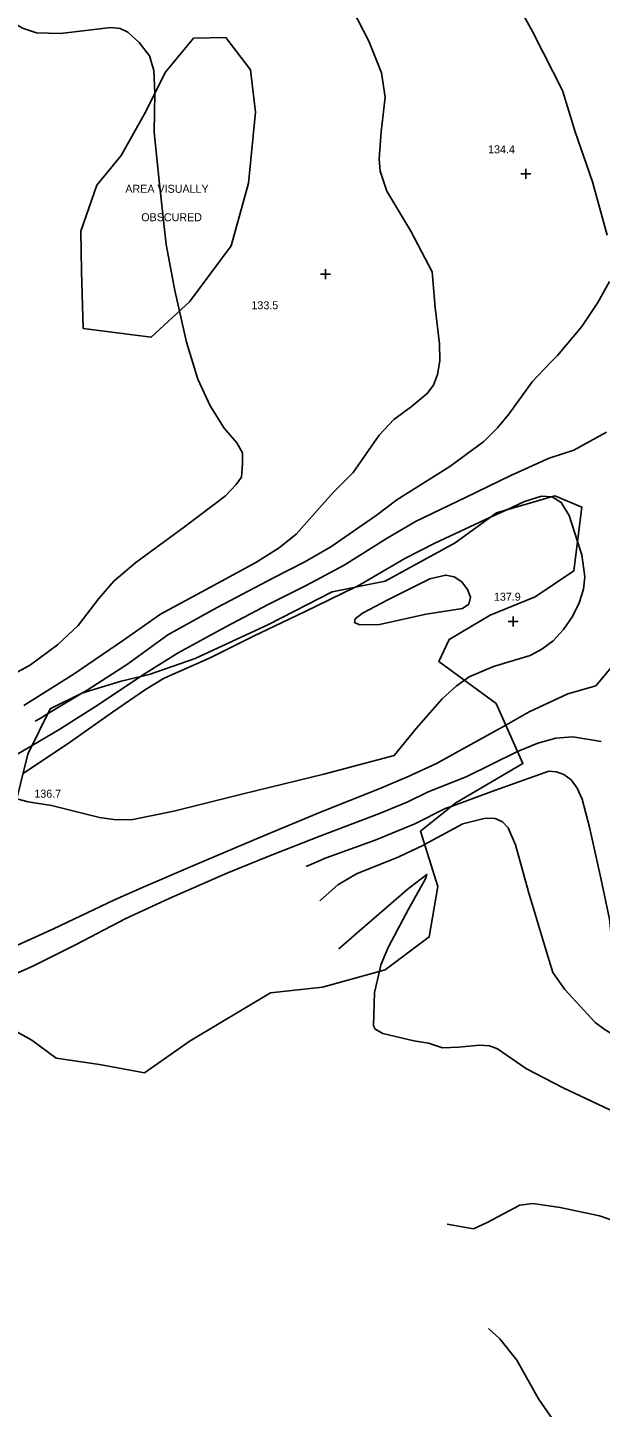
# Model space of a CAD drawing. Extents: x 1467615 to 2003689, y 770235 to 1108726.
# Drawn here: x 2002350.5 to 2002493.7, y 770841.8 to 771186.6 of the extents above; entities that cross this region are included whole.
import ezdxf

# ---------------------------------------------------------------- set-up
doc = ezdxf.new("R2010")
doc.units = 0
for name, color, linetype in [('RD_DTM_Major1', 7, 'Continuous'), ('RD_DTM_Major2', 7, 'Continuous'), ('RD_DTM_Minor1', 7, 'Continuous'), ('RD_DTM_Minor2', 7, 'Continuous'), ('RD_DTM_Obscure', 7, 'Continuous'), ('RD_DTM_Spot_Elev', 7, 'Continuous'), ('RD_TX_Misc1', 7, 'Continuous')]:
    doc.layers.add(name, color=color, linetype=linetype)

msp = doc.modelspace()

# ---------------------------------------------------------------- linework, layer by layer
at = {"layer": 'RD_DTM_Major1'}
for points in [[(2002437.97, 771234.89), (2002438.87, 771233.58), (2002445.32, 771226.37), (2002450.88, 771220.42), (2002458.65, 771210.24), (2002467.21, 771200), (2002472.79, 771192.64), (2002476.77, 771185.62), (2002481.91, 771175.42), (2002484.21, 771170.88), (2002487.38, 771160.55), (2002491.78, 771148.03), (2002495.42, 771134.7)], [(2002496.03, 771123.14), (2002493.09, 771117.87), (2002489.06, 771111.85), (2002483.02, 771104.66), (2002481.25, 771102.86), (2002476.67, 771098.08), (2002470.8, 771090), (2002467.99, 771086.57), (2002464.55, 771083.13), (2002456.12, 771076.93), (2002442.85, 771068.62), (2002437.65, 771064.68), (2002426.32, 771056.84), (2002419.87, 771053.12), (2002412.02, 771049.06), (2002397.94, 771041.69), (2002385.6, 771034.82), (2002375.51, 771027.5), (2002365.42, 771021.06), (2002364.25, 771020.35)], [(2002355.53, 771015.1), (2002353.68, 771013.99), (2002352.47, 771013.3)], [(2002473.03, 771005.67), (2002473.37, 771005.84), (2002478.04, 771007.82), (2002482.57, 771009.07), (2002486.81, 771009.34), (2002493.88, 771008.19)], [(2002465.72, 770861.55), (2002468.59, 770858.95), (2002472.79, 770853.64), (2002478.26, 770844), (2002482.78, 770837.46), (2002487.68, 770830.27), (2002489.58, 770825.77), (2002490.82, 770820.44), (2002492.47, 770804.83), (2002493.14, 770801.64), (2002494.31, 770799.47), (2002496.27, 770797.81), (2002504.44, 770793.62)]]:
    msp.add_lwpolyline(points, dxfattribs=at)
at = {"layer": 'RD_DTM_Major2'}
msp.add_line((2002364.25, 771020.35), (2002355.53, 771015.1), dxfattribs=at)
msp.add_lwpolyline([(2002341.81, 770947.7), (2002352.01, 770952.12), (2002362.55, 770957.4), (2002375.11, 770963.95), (2002385.95, 770968.99), (2002400.14, 770975.21), (2002410.86, 770979.52), (2002423.55, 770984.53), (2002438.54, 770990.19), (2002445.62, 770993.11), (2002450.68, 770995.65), (2002460.15, 770999.38), (2002473.03, 771005.67)], dxfattribs=at)
at = {"layer": 'RD_DTM_Minor1'}
for points in [[(2002430.3, 771193.91), (2002435.8, 771183.21), (2002438.98, 771175.26), (2002439.92, 771169.21), (2002438.94, 771160.49), (2002438.45, 771153.75), (2002438.65, 771150.68), (2002440.32, 771145.73), (2002446.34, 771135.68), (2002451.66, 771125.53), (2002452.44, 771116.65), (2002453.5, 771107.57), (2002453.56, 771103.3), (2002453.03, 771099.88), (2002451.96, 771097.22), (2002450.44, 771095.13), (2002446.45, 771091.82), (2002442.06, 771088.66), (2002438.39, 771084.72), (2002431.93, 771075.43), (2002426.94, 771070.38), (2002417.66, 771059.98), (2002413.45, 771056.62), (2002407.57, 771052.96), (2002398.09, 771047.74), (2002383.73, 771040.05), (2002374.53, 771033.56), (2002362.2, 771025.11), (2002349.57, 771017.23)], [(2002346.15, 771188.23), (2002349.24, 771186.4), (2002352.73, 771185.28), (2002358.73, 771185.06), (2002371.37, 771186.57), (2002373.65, 771186.36), (2002375.57, 771185.44), (2002378.41, 771182.8), (2002380.99, 771179.47), (2002382.07, 771175.83), (2002382.31, 771170.22), (2002382.31, 771170.08)], [(2002388.51, 771115.68), (2002390.27, 771107.93), (2002393.12, 771098.76), (2002396.2, 771092.03), (2002399.64, 771086.51), (2002402.86, 771082.85), (2002404.25, 771080.35), (2002404.25, 771077.56), (2002403.97, 771074.22), (2002402.66, 771072.4), (2002400.04, 771069.59), (2002389.75, 771061.83), (2002377.56, 771052.89), (2002372.08, 771048.25), (2002368.36, 771043.97), (2002363.21, 771037.19), (2002358.02, 771032.38), (2002351.23, 771027.39), (2002340.31, 771021.4), (2002334.23, 771017.87), (2002324.82, 771012.31), (2002317.66, 771007.73)], [(2002495.2, 771085.52), (2002487.08, 771081), (2002480.87, 771078.99), (2002471.48, 771074.73), (2002459.98, 771069.16), (2002447.66, 771063.23), (2002440.44, 771059.04), (2002429.65, 771052.3), (2002420.16, 771047.19), (2002410.7, 771042.4), (2002400.06, 771036.86), (2002388.21, 771030.37), (2002379.53, 771024.94), (2002378.73, 771024.41)], [(2002481.61, 771069.34), (2002479.01, 771069.46), (2002474.76, 771068.16), (2002470.3, 771066.1)], [(2002466.08, 771064.16), (2002464.81, 771063.57), (2002452.37, 771057.78), (2002444.85, 771053.91), (2002433.62, 771047.34), (2002432.38, 771046.74)], [(2002459.73, 771023.53), (2002460.9, 771024.35), (2002467, 771026.91), (2002476.13, 771029.71), (2002479.11, 771031.24), (2002481.94, 771033.35), (2002484.52, 771036.15), (2002486.72, 771039.42), (2002488.42, 771042.89), (2002489.5, 771046.27), (2002489.86, 771049.36), (2002489.09, 771054.84), (2002488.01, 771058.14)], [(2002470.06, 771012.31), (2002475.93, 771015.62), (2002485.61, 771020.09), (2002492.57, 771022.13), (2002496.94, 771027.3)], [(2002351.65, 771007.2), (2002346.26, 771004.03), (2002340.47, 771001.65), (2002335.57, 771000.36), (2002330.18, 770998.85), (2002325.33, 770996.8), (2002320.93, 770992.77), (2002319.36, 770991.29)], [(2002456.63, 770992.09), (2002467.5, 770996.08), (2002480.82, 771000.79), (2002482.72, 771000.63), (2002484.61, 770999.93), (2002486.39, 770998.6), (2002487.95, 770996.56), (2002489.2, 770993.76), (2002491.03, 770986.82), (2002493.79, 770974.07), (2002496.02, 770963.78), (2002497.38, 770950.37), (2002498.08, 770949.09), (2002499.26, 770948.11), (2002503.73, 770946.02), (2002514.91, 770941.81), (2002517.82, 770946.96)], [(2002449.77, 770982.48), (2002459.34, 770987.64), (2002465.01, 770989.08), (2002467.43, 770988.98), (2002469.28, 770988.14), (2002470.63, 770986.66), (2002472.46, 770982.41), (2002475.72, 770970.69), (2002479.97, 770956.5), (2002481.82, 770950.52), (2002484.83, 770946.24), (2002492.41, 770938.02), (2002494.89, 770936.19), (2002500.41, 770932.92), (2002504.77, 770930.82), (2002509.88, 770929.21), (2002515.45, 770928.74), (2002521.24, 770929.81), (2002528.73, 770932.65)], [(2002438.46, 770950.79), (2002437.24, 770945.49), (2002437.02, 770937.15), (2002437.39, 770936.36), (2002439.36, 770935.27), (2002447.11, 770933.43), (2002450.77, 770932.81), (2002454.21, 770931.71), (2002458.28, 770931.85), (2002463.62, 770932.38), (2002466.03, 770932.19), (2002468.01, 770931.44), (2002475.22, 770926.39), (2002484.44, 770921.7), (2002498.9, 770914.88), (2002505.92, 770910.8), (2002515.6, 770903.66), (2002525.72, 770895.19), (2002535.45, 770885.57), (2002545.38, 770875.06), (2002549.34, 770870.1), (2002558.62, 770864.92), (2002560.82, 770863.55)], [(2002455.45, 770887.59), (2002462, 770886.45), (2002465.43, 770888.01), (2002473.56, 770892.39), (2002476.83, 770892.76), (2002483.67, 770891.8), (2002493.47, 770889.68), (2002497.86, 770888.21)]]:
    msp.add_lwpolyline(points, dxfattribs=at)
at = {"layer": 'RD_DTM_Minor2'}
msp.add_line((2002470.3, 771066.1), (2002466.08, 771064.16), dxfattribs=at)
for points in [[(2002382.31, 771170.08), (2002382.2, 771160.41), (2002383.47, 771147.41), (2002385.19, 771132.33), (2002387.33, 771120.88), (2002388.51, 771115.68)], [(2002488.01, 771058.14), (2002485.89, 771064.66), (2002483.94, 771067.88), (2002481.63, 771069.34), (2002481.61, 771069.34)], [(2002450.14, 771040), (2002459.24, 771041.46), (2002460.87, 771042.55), (2002461.23, 771044.24), (2002460.52, 771046.22), (2002459.05, 771048.06), (2002457.13, 771049.35), (2002455.06, 771049.77), (2002451.09, 771048.86), (2002440.57, 771043.64), (2002434.25, 771040.3), (2002432.43, 771038.89), (2002432.29, 771037.9), (2002433.57, 771037.36), (2002438.46, 771037.43), (2002450.14, 771040)], [(2002432.38, 771046.74), (2002419.75, 771040.64), (2002407.01, 771034.56), (2002396.2, 771029.13), (2002384.69, 771024.06), (2002380, 771021.2), (2002371.79, 771015.55), (2002361.27, 771008.14), (2002349.4, 771000.21), (2002349.39, 771000.2)], [(2002347.82, 770993.85), (2002350.67, 770993.16), (2002356.52, 770992.22), (2002368.51, 770989.23), (2002372.71, 770988.67), (2002376.85, 770988.73), (2002387.12, 770990.76), (2002404.09, 770995.03), (2002424.62, 771000.06), (2002442.2, 771004.68), (2002447.65, 771011.45), (2002454.17, 771018.84), (2002457.63, 771022.05), (2002459.73, 771023.53)], [(2002378.73, 771024.41), (2002368.43, 771017.54), (2002358.58, 771011.27), (2002351.65, 771007.2)], [(2002264.94, 770921.43), (2002274.47, 770925.05), (2002284.9, 770929.15), (2002301.7, 770936.39), (2002318.69, 770943.9), (2002333.11, 770950.66), (2002344.36, 770955.65), (2002357.04, 770961.39), (2002372.25, 770968.64), (2002380.01, 770972.1), (2002392.42, 770977.4), (2002409.34, 770984.57), (2002423.73, 770990.58), (2002438.45, 770996.4), (2002445.46, 770999.39), (2002452.79, 771002.68), (2002462.87, 771008.25), (2002470.06, 771012.31)], [(2002420.21, 770976.98), (2002425.19, 770979.15), (2002437.4, 770983.56), (2002447.32, 770987.64), (2002454.93, 770991.46), (2002456.63, 770992.09)], [(2002423.6, 770968.4), (2002424.42, 770969.14), (2002428.08, 770972.43), (2002432.77, 770975.16), (2002443.33, 770979.43), (2002449.49, 770982.34), (2002449.77, 770982.48)], [(2002428.33, 770956.4), (2002432.88, 770960.37), (2002445.73, 770971.51), (2002450.37, 770975.01), (2002449.96, 770973.91), (2002445.72, 770966.33), (2002440.77, 770956.93), (2002438.83, 770952.38), (2002438.46, 770950.79)]]:
    msp.add_lwpolyline(points, dxfattribs=at)
at = {"layer": 'RD_DTM_Obscure'}
for points in [[(2002364.43, 771111.39), (2002364.04, 771125.67), (2002363.81, 771135.71), (2002367.83, 771147.2), (2002373.89, 771154.6), (2002380.13, 771165.62), (2002384.9, 771175.38), (2002392.02, 771183.88), (2002400.09, 771184.05), (2002406.26, 771176.02), (2002407.52, 771165.41), (2002405.78, 771147.66), (2002401.46, 771132.06), (2002391.05, 771118.01), (2002381.45, 771109.2), (2002364.43, 771111.39)], [(2002346.92, 770990.21), (2002350.59, 771005.05), (2002356.16, 771016.4), (2002364.12, 771020.31), (2002373.96, 771023.3), (2002380.95, 771024.93), (2002392.44, 771028.96), (2002410.75, 771037.4), (2002426.69, 771045.61), (2002439.93, 771048.24), (2002457.43, 771057.8), (2002467.71, 771065.36), (2002482.34, 771069.55), (2002489.09, 771066.78), (2002487.1, 771050.86), (2002477.4, 771044.34), (2002466.17, 771039.8), (2002455.91, 771033.72), (2002453.34, 771028.22), (2002467.65, 771017.72), (2002474.36, 771002.7), (2002457.61, 770992.87), (2002448.73, 770985.78), (2002453.08, 770972), (2002450.95, 770959.39), (2002439.91, 770951.19), (2002424.25, 770946.87), (2002411.27, 770945.39), (2002391.2, 770933.45), (2002379.78, 770925.46), (2002368.53, 770927.5), (2002357.65, 770929.11), (2002351.6, 770933.59), (2002343.3, 770938.15)]]:
    msp.add_lwpolyline(points, dxfattribs=at)
at = {"layer": 'RD_DTM_Spot_Elev'}
for p, q in [((2002473.8, 771150.05), (2002476.3, 771150.05)), ((2002475.05, 771148.8), (2002475.05, 771151.3)), ((2002423.75, 771125), (2002426.25, 771125)), ((2002425, 771123.75), (2002425, 771126.25)), ((2002471.95, 771036.93), (2002471.95, 771039.43)), ((2002470.7, 771038.18), (2002473.2, 771038.18))]:
    msp.add_line(p, q, dxfattribs=at)

# ---------------------------------------------------------------- texts
for s, p in [('134.4', (2002465.65, 771155.15)), ('133.5', (2002406.5, 771116.19)), ('137.9', (2002467.11, 771043.38)), ('136.7', (2002352.23, 770994.17))]:
    msp.add_text(s, height=2, dxfattribs=at).set_placement(p)
at = {"layer": 'RD_TX_Misc1'}
for s, p in [('AREA VISUALLY', (2002374.98, 771145.29)), ('OBSCURED', (2002378.96, 771138.18))]:
    msp.add_text(s, height=2, dxfattribs=at).set_placement(p)

doc.saveas('drawing.dxf')
